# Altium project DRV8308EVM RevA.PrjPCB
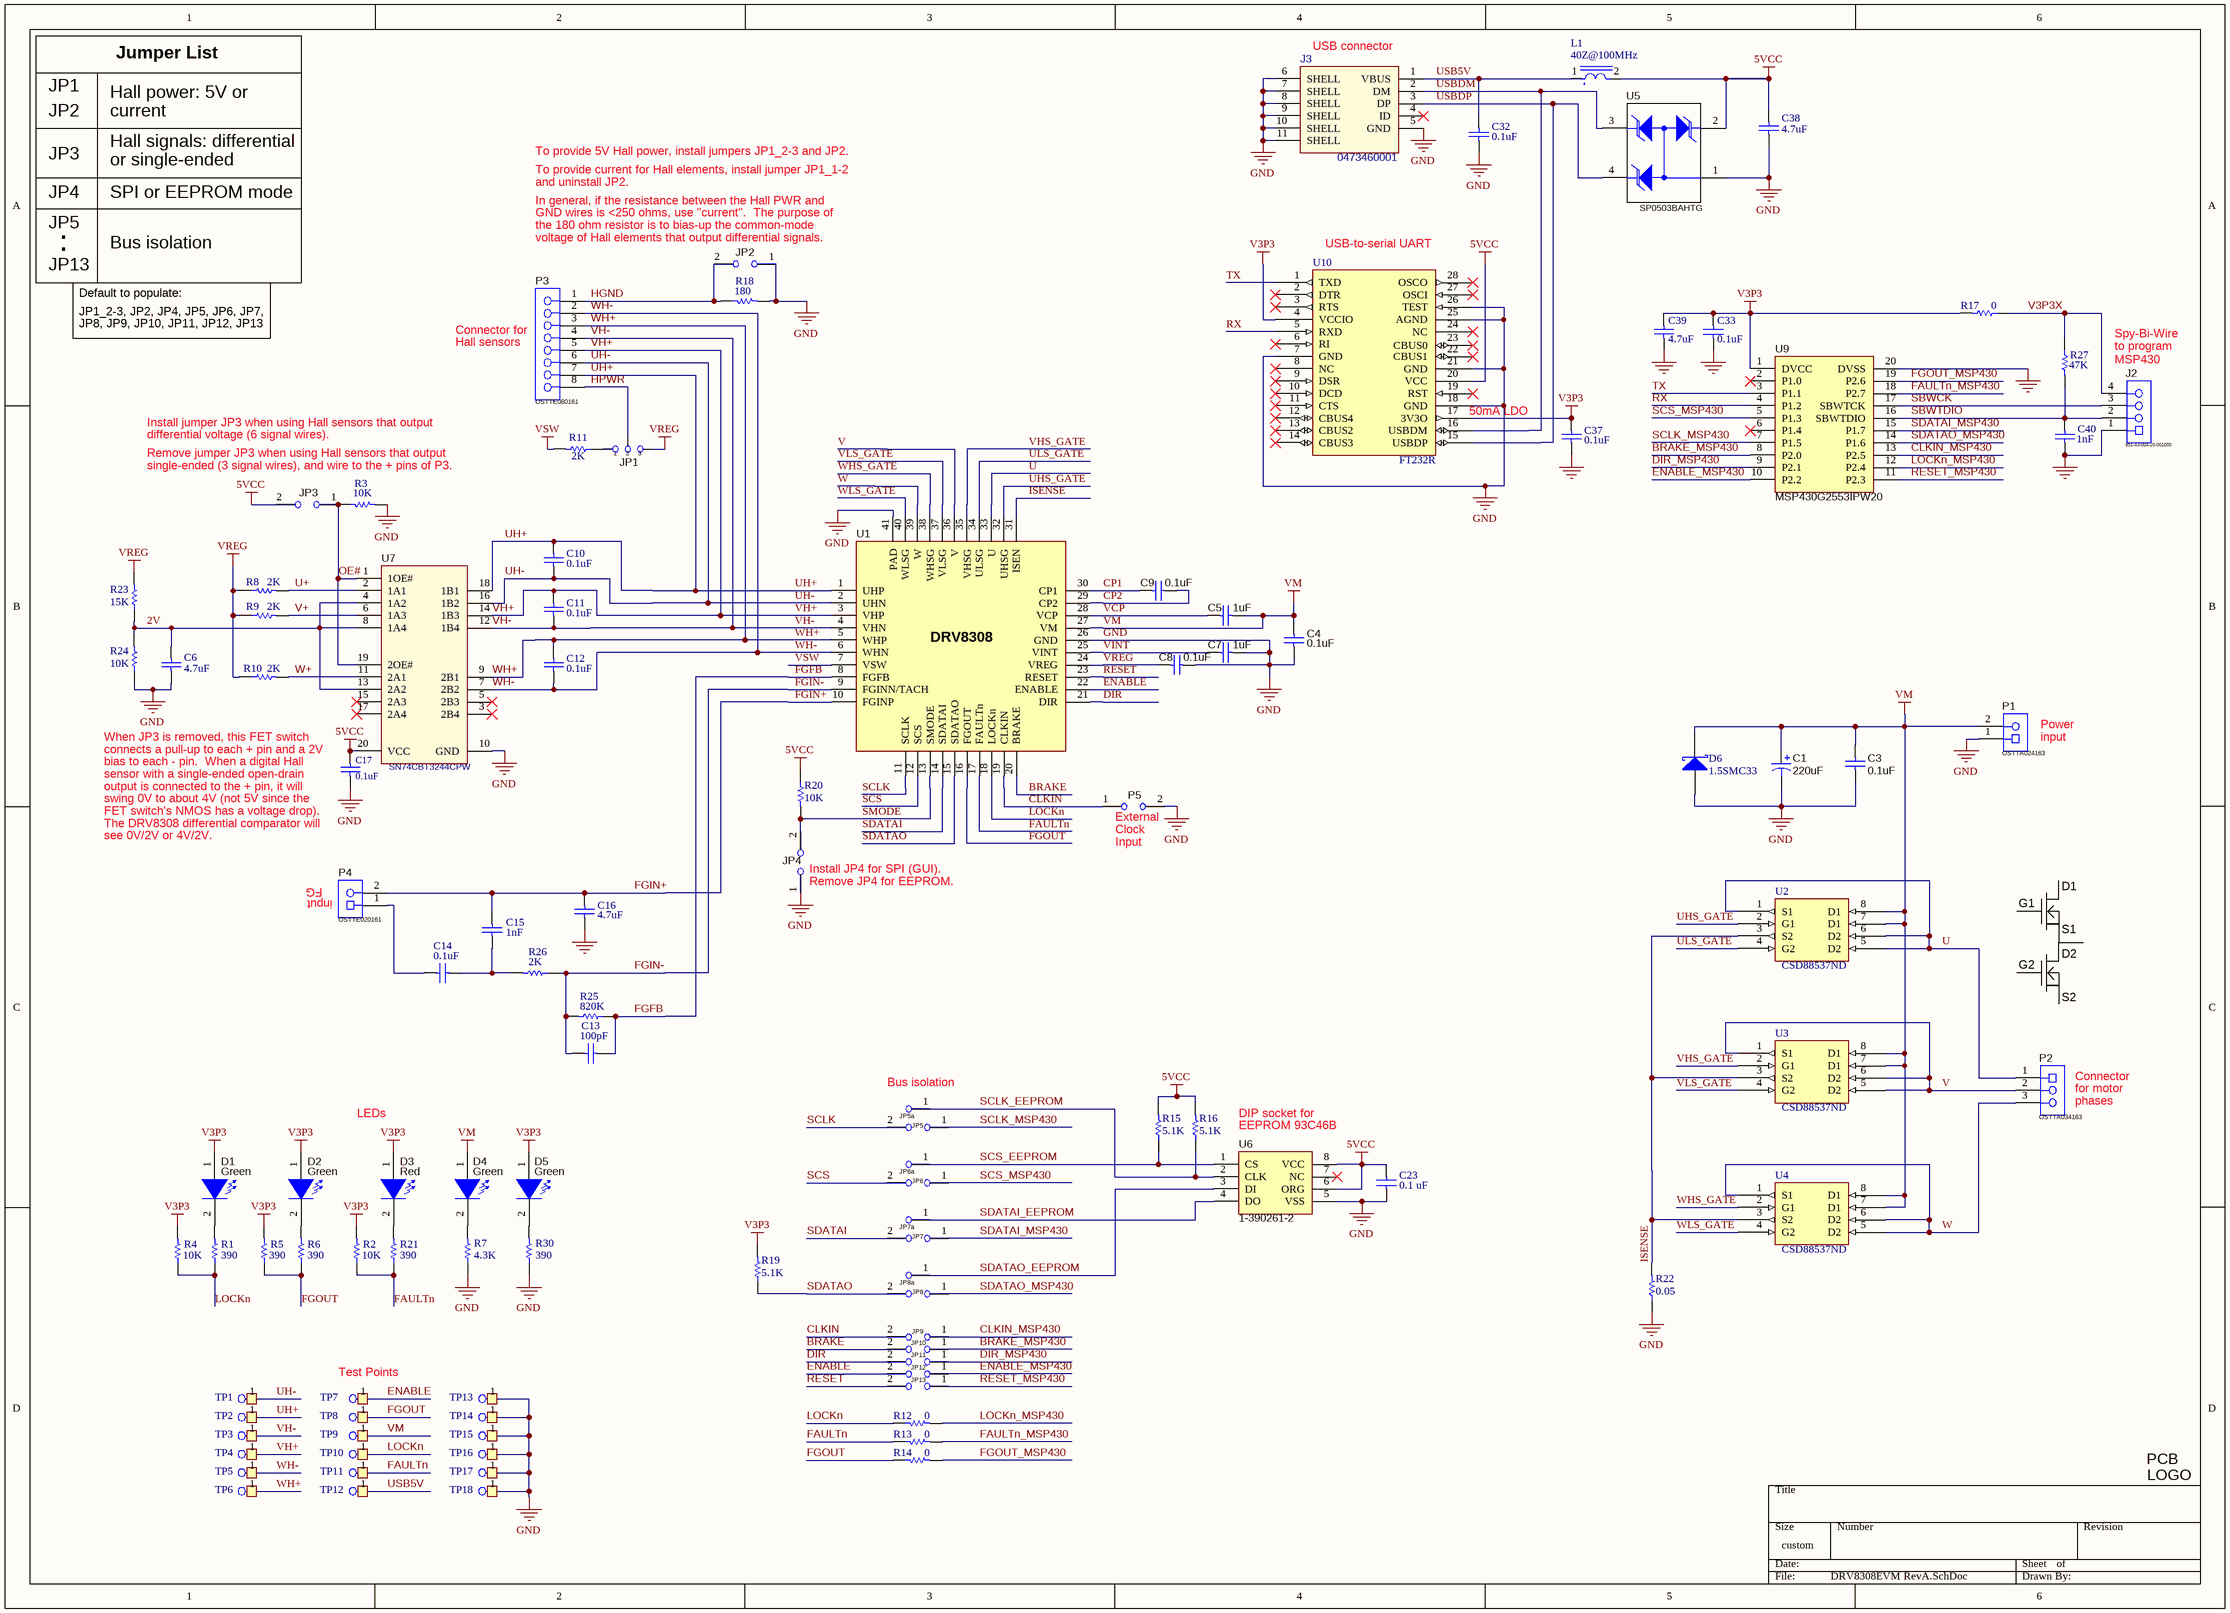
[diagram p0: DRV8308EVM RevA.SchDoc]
CopyrightYear: 2012; PCB_Layout: Who did the Layout?; PCB_Rev: E1; PRJ_Customer: Public Release; PRJ_Engineer: Enter name of project lead; PRJ_Number: XX####; PRJ_Title: Change in menu Project|Project Options|Parameters; SCH_Rev: E1; TechSupport: http://www.ti.com/support
1 sheet, 110 parts. Net scope: global (net labels, ports and power ports of the same name join across sheets).
Board file: DRV8308EVM RevA.PcbDoc

## Sheet DRV8308EVM RevA.SchDoc
size 457 x 330 mm

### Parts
C1  220uF  [UVZ1J221MPD_fp]
C3  ValueDisplayed: 0.1uF  [0603]  (hidden comment: 06031C272JAT2A)
C4  ValueDisplayed: 0.1uF  [0603]  (hidden comment: 06031C272JAT2A)
C5  ValueDisplayed: 1uF  [0603]  (hidden comment: 06031C272JAT2A)
C6  value 4.7uF  [0805]
C7  ValueDisplayed: 1uF  [0603]  (hidden comment: 06031C272JAT2A)
C8  value 0.1uF  [0805]
C9  value 0.1uF  [0805]
C10  0.1uF  [0805]
C11  0.1uF  [0805]
C12  0.1uF  [0805]
C13  value 100pF  [0805]
C14  value 0.1uF  [0805]
C15  value 1nF  [0805]
C16  value 4.7uF  [0805]
C17  value 0.1uF  [0805]  (hidden comment: Cap)
C23  value 0.1 uF  [0805]
C32  value 0.1uF  [0805]  (hidden comment: Cap)
C33  ValueDisplayed: 0.1uF  [0603]  (hidden comment: 06031C272JAT2A)
C37  value 0.1uF  [0805]  (hidden comment: Cap)
C38  value 4.7uF  [0805]
C39  value 4.7uF  [0805]
C40  value 1nF  [0805]
D1  value Green  [LED_LTST-C171]  (hidden comment: LTST-C171GKT)
D2  value Green  [LED_LTST-C171]  (hidden comment: LTST-C171GKT)
D3  value Red  [LED_LTST-C170]  (hidden comment: LTST-C170KRKT)
D4  value Green  [LED_LTST-C171]  (hidden comment: LTST-C171GKT)
D5  value Green  [LED_LTST-C171]  (hidden comment: LTST-C171GKT)
D6  1.5SMC33  [SMC-W]
J2  851-43-004-20-001000  [CONN_851-43-004-20-001000]
J3  0473460001  [CONN_47346-0001]
JP1  Pin1: 1  Pin2: 2  Pin3: 3  [HDR100_1X3]  (hidden comment: JUMPER_3X100MIL)
JP2  JUMPER_2X100MIL  [2PIN HEADER]  (value not drawn)
JP3  JUMPER_2X100MIL  [2PIN HEADER]  (value not drawn)
JP4  JUMPER_2X100MIL  [2PIN HEADER]  (value not drawn)
JP5  JUMPER_2X100MIL  [2PIN HEADER]  (value not drawn)
JP5a  (no value)  [1x1 Header]
JP6  JUMPER_2X100MIL  [2PIN HEADER]  (value not drawn)
JP6a  (no value)  [1x1 Header]
JP7  JUMPER_2X100MIL  [2PIN HEADER]  (value not drawn)
JP7a  (no value)  [1x1 Header]
JP8  JUMPER_2X100MIL  [2PIN HEADER]  (value not drawn)
JP8a  (no value)  [1x1 Header]
JP9  JUMPER_2X100MIL  [2PIN HEADER]  (value not drawn)
JP10  JUMPER_2X100MIL  [2PIN HEADER]  (value not drawn)
JP11  JUMPER_2X100MIL  [2PIN HEADER]  (value not drawn)
JP12  JUMPER_2X100MIL  [2PIN HEADER]  (value not drawn)
JP13  JUMPER_2X100MIL  [2PIN HEADER]  (value not drawn)
L1  40Z@100MHz  [0805]
LOGO  Texas Instruments  [TI_Stacked_Overlay_Medium]  (value not drawn)  (no BOM)
P1  OSTTA024163  [On-Shore_OSTTA024163]
P2  OSTTA034163  [On-Shore_OSTTA034163]
P3  OSTTE080161  [On-Shore_OSTTE080161]
P4  OSTTE020161  [On-Shore_OSTTE020161]
P5  JUMPER_2X100MIL  [2PIN HEADER]  (value not drawn)
R1  390  [0805]
R2  10K  [0805]
R3  10K  [0805]
R4  10K  [0805]
R5  390  [0805]
R6  390  [0805]
R7  value 4.3K  [0805]  (hidden comment: Res1)
R8  value 2K  [0805]
R9  value 2K  [0805]
R10  value 2K  [0805]
R11  2K  [0805]
R12  0  [0805]
R13  0  [0805]
R14  0  [0805]
R15  value 5.1K  [0805L]  (hidden comment: 1-1614959-1)
R16  value 5.1K  [0805L]  (hidden comment: 1-1614959-1)
R17  0  [0805]
R18  180  [0805]
R19  5.1K  [0805]
R20  10K  [0805]
R21  390  [0805]
R22  value 0.05  [2512M]
R23  value 15K  [0805]
R24  value 10K  [0805]
R25  820K  [0805]
R26  2K  [0805]
R27  47K  [0805]
R30  value 390  [0805]  (hidden comment: Res1)
TP1  TP-LOOP-ORANGE  [TEST POINT 0.052]  (value not drawn)
TP2  TP-LOOP-ORANGE  [TEST POINT 0.052]  (value not drawn)
TP3  TP-LOOP-ORANGE  [TEST POINT 0.052]  (value not drawn)
TP4  TP-LOOP-ORANGE  [TEST POINT 0.052]  (value not drawn)
TP5  TP-LOOP-ORANGE  [TEST POINT 0.052]  (value not drawn)
TP6  TP-LOOP-ORANGE  [TEST POINT 0.052]  (value not drawn)
TP7  TP-LOOP-ORANGE  [TEST POINT 0.052]  (value not drawn)
TP8  TP-LOOP-ORANGE  [TEST POINT 0.052]  (value not drawn)
TP9  TP-LOOP-ORANGE  [TEST POINT 0.052]  (value not drawn)
TP10  TP-LOOP-BLACK  [TEST POINT 0.052]  (value not drawn)
TP11  TP-LOOP-ORANGE  [TEST POINT 0.052]  (value not drawn)
TP12  TP-LOOP-ORANGE  [TEST POINT 0.052]  (value not drawn)
TP13  TP-LOOP-BLACK  [TEST POINT 0.052]  (value not drawn)
TP14  TP-LOOP-BLACK  [TEST POINT 0.052]  (value not drawn)
TP15  TP-LOOP-ORANGE  [TEST POINT 0.052]  (value not drawn)
TP16  TP-LOOP-BLACK  [TEST POINT 0.052]  (value not drawn)
TP17  TP-LOOP-BLACK  [TEST POINT 0.052]  (value not drawn)
TP18  TP-LOOP-BLACK  [TEST POINT 0.052]  (value not drawn)
U1  DRV8308  [RHA0040A]
U2  CSD88537ND  [SO-8_N]
U3  CSD88537ND  [SO-8_N]
U4  CSD88537ND  [SO-8_N]
U5  SP0503BAHTG  [SOT-143-4]
U6  1-390261-2  [TE_1-390261-2]
U7  SN74CBT3244CPW  [PW0020A_N]
U9  MSP430G2553IPW20  [PW20]
U10  FT232R  [FT232RL]

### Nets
5VCC: C17.2 C23.1 C38.1 JP3.2 L1.2 R15.2 R16.2 R20.1 U5.2(K1) U6.6(ORG) U6.8(VCC) U7.20(VCC) U10.20(VCC)
GND: C1.2(-) C3.2 C4.2 C6.2 C7.2 C8.1 C16.1 C17.1 C23.2 C32.1 C33.2 C37.1 C38.2 C39.2 C40.1 D6.1(A) J2.1 J3.5(GND) J3.6(SHELL) J3.7(SHELL) J3.8(SHELL) J3.9(SHELL) J3.10(SHELL) J3.11(SHELL) JP2.1 JP4.1 P1.1 P5.2 R3.2 R7.1 R18.2 R22.1 R24.1 R30.1 TP13.1 TP14.1 TP15.1 TP16.1 TP17.1 TP18.1 U1.26(GND) U1.41(PAD) U5.1(A) U6.5(VSS) U7.10(GND) U9.20(DVSS) U10.7(GND) U10.18(GND) U10.21(GND) U10.25(AGND) U10.26(TEST)
V3P3: C33.1 C37.2 C39.1 D1.1(A) D2.1(A) D3.1(A) D5.1(A) R2.2 R4.2 R5.2 R17.2 R19.2 U9.1(DVCC) U10.4(VCCIO) U10.17(3V3O)
VM: C1.1(+) C3.1 C4.1 C5.2 D4.1(A) D6.2(K) P1.2 TP9.1 U1.27(VM) U2.7(D1) U2.8(D1) U3.7(D1) U3.8(D1) U4.7(D1) U4.8(D1)
VREG: C8.2 JP1.3 R8.1 R9.1 R10.1 R23.2 U1.24(VREG)
VSW: R11.2 U1.7(VSW)
2V: C6.1 R23.1 R24.2 U7.4(1A2) U7.8(1A4) U7.13(2A2)
BRAKE: JP10.2 U1.20(BRAKE)
BRAKE_MSP430: JP10.1 U9.8(P2.0)
CLKIN: JP9.2 P5.1 U1.19(CLKIN)
CLKIN_MSP430: JP9.1 U9.13(P2.5)
CP1: C9.2 U1.30(CP1)
CP2: C9.1 U1.29(CP2)
DIR: JP11.2 U1.21(DIR)
DIR_MSP430: JP11.1 U9.9(P2.1)
ENABLE: JP12.2 TP7.1 U1.22(ENABLE)
ENABLE_MSP430: JP12.1 U9.10(P2.2)
FAULTn: R2.1 R13.1 R21.1 TP11.1 U1.17(FAULTn)
FAULTn_MSP430: R13.2 U9.18(P2.7)
FGFB: C13.2 R25.1 U1.8(FGFB)
FGIN+: C15.1 C16.2 P4.2 U1.10(FGINP)
FGIN-: C13.1 R25.2 R26.1 U1.9(FGINN/TACH)
FGOUT: R5.1 R6.1 R14.1 TP8.1 U1.16(FGOUT)
FGOUT_MSP430: R14.2 U9.19(P2.6)
HGND: JP2.2 P3.1 R18.1
HPWR: JP1.2 P3.8
ISENSE: R22.2 U1.31(ISEN) U2.3(S2) U3.3(S2) U4.3(S2)
LOCKn: R1.1 R4.1 R12.1 TP10.1 U1.18(LOCKn)
LOCKn_MSP430: R12.2 U9.12(P2.4)
OE#: JP3.1 R3.1 U7.1(1OE#) U7.19(2OE#)
RESET: JP13.2 U1.23(RESET)
RESET_MSP430: JP13.1 U9.11(P2.3)
RX: U9.4(P1.2) U10.5(RXD)
SBWCK: J2.3 U9.17(SBWTCK)
SBWTDIO: C40.2 J2.2 R27.2 U9.16(SBWTDIO)
SCLK: JP5.2 U1.11(SCLK)
SCLK_EEPROM: JP5a.1 R16.1 U6.2(CLK)
SCLK_MSP430: JP5.1 U9.7(P1.5)
SCS: JP6.2 U1.12(SCS)
SCS_EEPROM: JP6a.1 R15.1 U6.1(CS)
SCS_MSP430: JP6.1 U9.5(P1.3)
SDATAI: JP7.2 U1.14(SDATAI)
SDATAI_EEPROM: JP7a.1 U6.4(DO)
SDATAI_MSP430: JP7.1 U9.15(P1.7)
SDATAO: JP8.2 R19.1 U1.15(SDATAO)
SDATAO_EEPROM: JP8a.1 U6.3(DI)
SDATAO_MSP430: JP8.1 U9.14(P1.6)
SMODE: JP4.2 R20.2 U1.13(SMODE)
TX: U9.3(P1.1) U10.1(TXD)
U: P2.1 U1.33(U) U2.1(S1) U2.5(D2) U2.6(D2)
U+: R8.2 U7.2(1A1)
UH+: C10.2 P3.7 TP2.1 U1.1(UHP) U7.18(1B1)
UH-: C10.1 P3.6 TP1.1 U1.2(UHN) U7.16(1B2)
UHS_GATE: U1.32(UHSG) U2.2(G1)
ULS_GATE: U1.34(ULSG) U2.4(G2)
USB5V: C32.2 J3.1(VBUS) L1.1 TP12.1
USBDM: J3.2(DM) U5.3(K2) U10.16(USBDM)
USBDP: J3.3(DP) U5.4(K3) U10.15(USBDP)
V: P2.2 U1.36(V) U3.1(S1) U3.5(D2) U3.6(D2)
V3P3X: J2.4 R17.1 R27.1
V+: R9.2 U7.6(1A3)
VCP: C5.1 U1.28(VCP)
VH+: C11.2 P3.5 TP4.1 U1.3(VHP) U7.14(1B3)
VH-: C11.1 P3.4 TP3.1 U1.4(VHN) U7.12(1B4)
VHS_GATE: U1.35(VHSG) U3.2(G1)
VINT: C7.1 U1.25(VINT)
VLS_GATE: U1.37(VLSG) U3.4(G2)
W: P2.3 U1.39(W) U4.1(S1) U4.5(D2) U4.6(D2)
W+: R10.2 U7.11(2A1)
WH+: C12.2 P3.3 TP6.1 U1.5(WHP) U7.9(2B1)
WH-: C12.1 P3.2 TP5.1 U1.6(WHN) U7.7(2B2)
WHS_GATE: U1.38(WHSG) U4.2(G1)
WLS_GATE: U1.40(WLSG) U4.4(G2)
NetC14_1: C14.1 P4.1
NetC14_2: C14.2 C15.2 R26.2
NetD1_2: D1.2(K) R1.2
NetD2_2: D2.2(K) R6.2
NetD3_2: D3.2(K) R21.2
NetD4_2: D4.2(K) R7.2
NetD5_2: D5.2(K) R30.2
NetJP1_1: JP1.1 R11.1

Not connected (* = marked no-connect by the designer): J3 4(ID)*; U6 7(NC)*; U7 3(2B4)* 5(2B3)* 15(2A3)* 17(2A4)*; U9 2(P1.0)* 6(P1.4)*; U10 2(DTR)* 3(RTS)* 6(RI)* 8(NC)* 9(DSR)* 10(DCD)* 11(CTS)* 12(CBUS4)* 13(CBUS2)* 14(CBUS3)* 19(RST)* 22(CBUS1)* 23(CBUS0)* 24(NC)* 27(OSCI)* 28(OSCO)*

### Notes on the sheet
- Jumper List
- (near J3) USB connector
- JP1
- JP2
- Hall signals: differential
- Hall power: 5V or
- current
- To provide 5V Hall power, install jumpers JP1_2-3 and JP2.
- JP3
- JP4
- SPI or EEPROM mode
- or single-ended
- To provide current for Hall elements, install jumper JP1_1-2
- and uninstall JP2.
- In general, if the resistance between the Hall PWR and
- JP5
- JP13
- .
- Bus isolation
- (near JP2) GND wires is <250 ohms, use "current".  The purpose of
- (near JP2) the 180 ohm resistor is to bias-up the common-mode
- (near JP2) voltage of Hall elements that output differential signals.
- (near U10) USB-to-serial UART
- Default to populate:
- JP1_2-3, JP2, JP4, JP5, JP6, JP7,
- JP8, JP9, JP10, JP11, JP12, JP13
- (near P3) Connector for
- Spy-Bi-Wire
- (near P3) Hall sensors
- to program
- (near J2) MSP430
- Install jumper JP3 when using Hall sensors that output
- Remove jumper JP3 when using Hall sensors that output
- differential voltage (6 signal wires).
- (near U10) 50mA LDO
- single-ended (3 signal wires), and wire to the + pins of P3.
- (near C17) When JP3 is removed, this FET switch
- (near C17) connects a pull-up to each + pin and a 2V
- (near C17) bias to each - pin.  When a digital Hall
- (near P1) Power
- (near P1) input
- (near C17) sensor with a single-ended open-drain
- (near C17) output is connected to the + pin, it will
- (near C17) swing 0V to about 4V (not 5V since the
- (near C17) FET switch's NMOS has a voltage drop).
- The DRV8308 differential comparator will
- (near P5) External
- see 0V/2V or 4V/2V.
- (near P4) FG
- (near P4) input
- (near JP4) Install JP4 for SPI (GUI).
- (near JP4) Remove JP4 for EEPROM.
- (near P5) Input
- (near P5) Clock
- D1
- G1
- S1
- G2
- D2
- S2
- LEDs
- (near JP5a) Bus isolation
- DIP socket for
- EEPROM 93C46B
- (near P2) Connector
- (near P2) for motor
- (near P2) phases
- (near TP7) Test Points

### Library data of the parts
C1 = UVZ1J221MPD: SymbolVersion: use current date i.e. 2008-05-20; SymbolCreator: Use a-id; CompType: Used in some BOM reports.  Useful for finding later.; U/M: EA, IN, or GM
C3-C5 C7 C33 = 06031C272JAT2A: CAP, CERM, 2700pF, 100V, +/-5%, X7R, 0603; Manufacturer: AVX; Polarized: N; CompType: Capacitor; U/M: EA; Cap_F: 0.0000000027; Tolerance_%: 5; ESR_Ohm: 0.174; Value1: 0.174 ohm; VDC_V: 100; TaMin_C: -55; TaMax_C: 125
C6 C8-C17 C23 C32 C37-C40 = Cap: Capacitor
D1 D2 D4 D5 = LTST-C171GKT: LED, Green, SMD; Manufacturer: Lite-On; Type: AlInGaP; Vf_V: 2.1; Value2: 2.1V; Io_A: 20; Value1: W; U/M: EA
D3 = LTST-C170KRKT: LED, Red, SMD; Manufacturer: Lite-On; Type: AlInGaP; Vf_V: 2; Value2: 2V; Io_A: 20; Value1: W; U/M: EA
D6 = D Schottky: Schottky Diode
J2 = 851-43-004-20-001000_nosilk: MSP430 programming connector; Manufacturer: Mill-Max; DK Part Number: ED90474-ND; Description: Header for MSP430
J3 = USB Micro B
JP1 = JUMPER_3X100MIL: Header, Male 3-pin, 100mil spacing,
JP2-JP13 P5 = JUMPER_2X100MIL: Header, Male 2-pin, 100mil spacing,
JP5a JP6a JP7a JP8a = 1x1 Header
L1 = BEAD_FERRITE_MPZ2012_SERIES: Bead, Ferrite, yymA, yyOhm @100KHz
LOGO = TI_Logo: Texas Instrument Corporate Signature; SymbolCreator: a0412235
P1 = OSTTA024163: Terminal Block, 2x1, 5.08mm, TH; Manufacturer: On-Shore Technology; SymbolCreator: a0412235; U/M: EA
P2 = OSTTA034163: Terminal Block, 3x1, 5.08 mm, TH; Manufacturer: On-Shore Technology; SymbolCreator: a0412235; U/M: EA
P3 = OSTTE080161: Terminal Block, 8x1, 3.5mm, TH; Manufacturer: On-Shore Technology; SymbolCreator: a0411947; U/M: EA
P4 = OSTTE020161: Terminal Block, 2x1, 3.5mm, TH; Manufacturer: On-Shore Technology; SymbolCreator: a0412235; U/M: EA
R1-R14 R17-R21 R23-R27 R30 = Res1: Resistor
R15 R16 = 1-1614959-1: RES, 1.50Meg ohm, 0.1%, 0.1W, 0805; Manufacturer: Tyco Electronics; CompType: Resistor; Res_ohm: 1500000; Value_Code: 1M50; Tolerance_%: 0.1; VDC_V: 50; TempCo: 25 ppm/C; EIA_Code: E192; U/M: EA
R22 = CSRN2512FK30L0: RES, 0.03 ohm, 1%, 2W, 2512
TP1-TP18 = TEST POINT: Glass Beaded Test Point
U2-U4 = FDS8949: MOSFET N-CH DUAL 30V 3.5A SOP8
U5 = SP0503BAHTG: Diode, TVS, Uni, 5.5V, W, 3.04X1.22X1.4; Manufacturer: Littelfuse; SymbolCreator: x0208326; U/M: EA; Power_W: 0.225; Vr_V: 5.5; Value1: 0.225W
U6 = 1-390261-2: Socket, DIP-8 TIN, TH; Manufacturer: TE Connectivity; SymbolCreator: a0799628; U/M: EA
U9 = MSP430G2553IPW20_sm
U10 = FT232R: USB Chip

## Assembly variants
001: all parts fitted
